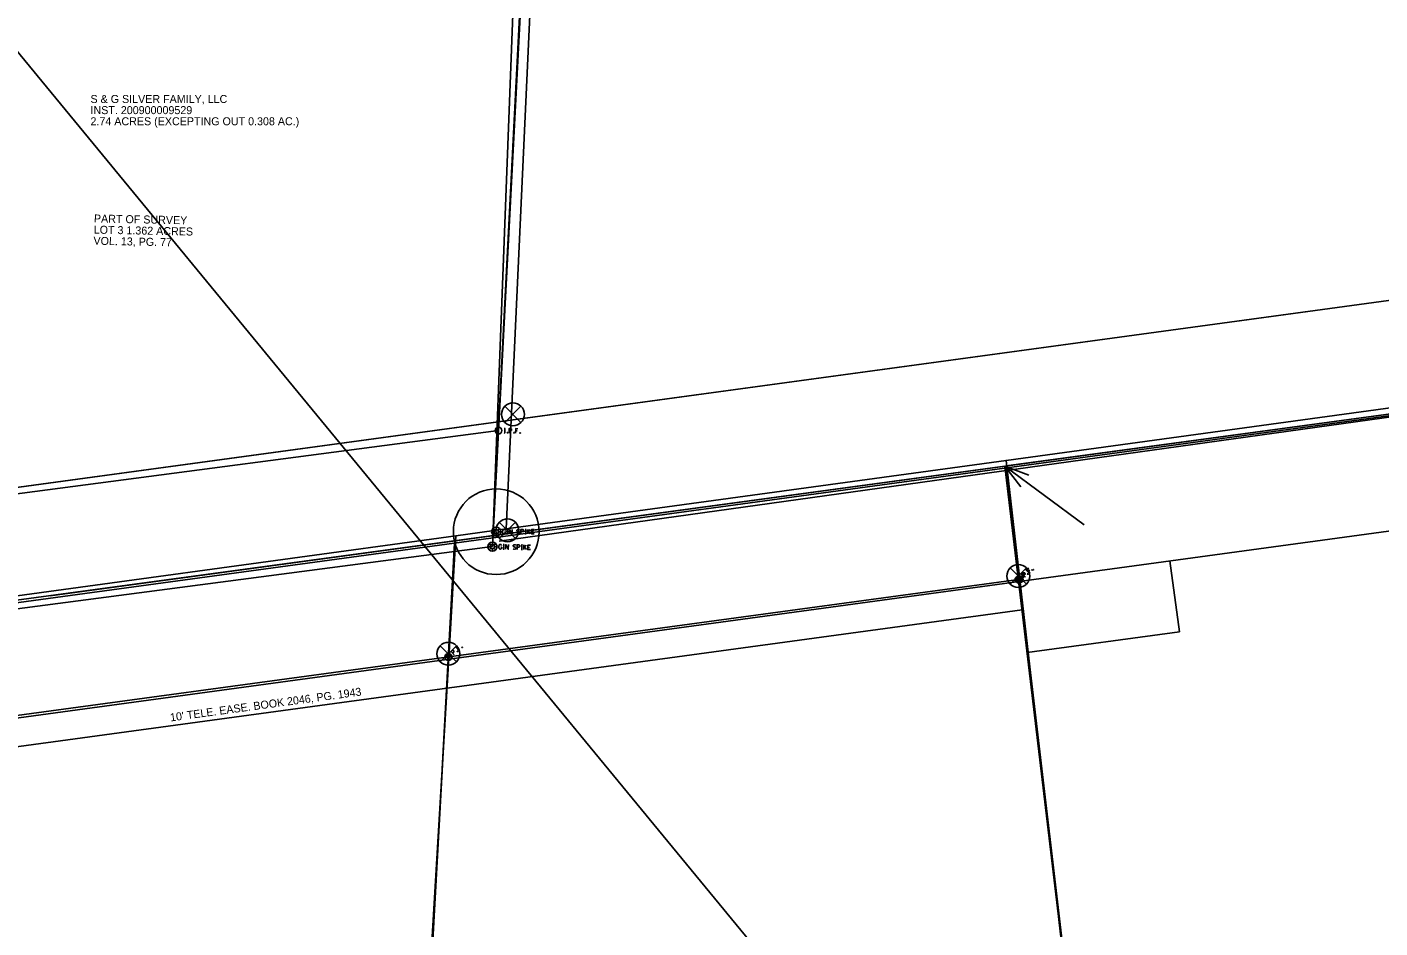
# Model space of a CAD drawing. Extents: x 1532954 to 1577849, y 698998 to 706606.
# Drawn here: x 1572033.3 to 1572506.6, y 702785.4 to 703100.9 of the extents above; entities that cross this region are included whole.
import ezdxf

# ---------------------------------------------------------------- set-up
doc = ezdxf.new("R2010")
doc.units = 0
for name, color, linetype in [('Default', 7, 'Continuous'), ('DV_X_Lot_Line', 7, 'Continuous'), ('DV_X_Property_Line', 7, 'Continuous'), ('GM_X_Major_Lake', 7, 'Continuous'), ('RW_X_Esmt_SH', 7, 'Continuous'), ('RW_X_Esmt_U', 7, 'Continuous'), ('RW_X_Text', 7, 'Continuous'), ('SC_Scratch1', 7, 'Continuous'), ('SC_Scratch10', 7, 'Continuous'), ('SC_Scratch2', 7, 'Continuous'), ('SC_Scratch3', 7, 'Continuous'), ('SC_Scratch4', 7, 'Continuous'), ('SC_Scratch9', 7, 'Continuous'), ('SV_X_Control_Cells_Found', 7, 'Continuous')]:
    doc.layers.add(name, color=color, linetype=linetype)

msp = doc.modelspace()

# ---------------------------------------------------------------- linework, layer by layer
at = {"layer": 'Default'}
for p, q in [((1572200.46, 702968.09), (1572206.12, 702962.43)), ((1572200.46, 702962.43), (1572206.12, 702968.09)), ((1572203.29, 702965.26), (1572203.29, 702965.26)), ((1572198.54, 702927.46), (1572204.2, 702921.8)), ((1572198.54, 702921.8), (1572204.2, 702927.46)), ((1572201.37, 702924.63), (1572201.37, 702924.63)), ((1572377.28, 702911.48), (1572382.94, 702905.82)), ((1572377.28, 702905.82), (1572382.94, 702911.48)), ((1572380.11, 702908.65), (1572380.11, 702908.65)), ((1572177.88, 702884.27), (1572183.54, 702878.61)), ((1572177.88, 702878.61), (1572183.54, 702884.27)), ((1572180.71, 702881.44), (1572180.71, 702881.44))]:
    msp.add_line(p, q, dxfattribs=at)
for centre in [(1572203.29, 702965.26), (1572201.37, 702924.63), (1572380.11, 702908.65), (1572180.71, 702881.44)]:
    msp.add_circle(centre, 4, dxfattribs=at)
at = {"layer": 'DV_X_Lot_Line'}
msp.add_line((1572166.48, 702619.22), (1572182.89, 702920.2), dxfattribs=at)
at = {"layer": 'DV_X_Property_Line'}
for p, q in [((1572245.38, 703873.46), (1572196.21, 702922.02)), ((1572416.09, 702605.27), (1572375.54, 702946.46))]:
    msp.add_line(p, q, dxfattribs=at)
at = {"layer": 'GM_X_Major_Lake'}
for p, q in [((1572436.47, 702889.16), (1572433.1, 702913.93)), ((1572383.21, 702881.9), (1572380.26, 702906.73)), ((1572383.21, 702881.9), (1572436.47, 702889.16))]:
    msp.add_line(p, q, dxfattribs=at)
at = {"layer": 'RW_X_Esmt_SH'}
for p, q in [((1571959, 702849.32), (1574870.56, 703246.15)), ((1571963.78, 702930.71), (1573359.47, 703120.93))]:
    msp.add_line(p, q, dxfattribs=at)
at = {"layer": 'RW_X_Esmt_U'}
msp.add_line((1571958.43, 702839.15), (1572381.44, 702896.8), dxfattribs=at)
at = {"layer": 'SC_Scratch1'}
for points in [[(1572687.31, 702991.85), (1572375.87, 702949.15), (1572200.89, 702925.16), (1572202.78, 702965.79), (1572209.37, 703107.62), (1572211.69, 703157.56), (1572219.71, 703329.96), (1572219.71, 703329.96), (1572224.35, 703429.86), (1572229.46, 703539.74), (1572237.01, 703702.1), (1572244.56, 703864.45), (1573202.26, 703819.91)], [(1572365.62, 701708.75), (1572371.48, 701808.58), (1572376.97, 701902.02), (1572377.3, 701908.41), (1572382.44, 702008.28), (1572387.57, 702108.15), (1572392.71, 702208.02), (1572397.85, 702307.89), (1572401.43, 702377.55), (1572403.22, 702407.75), (1572409.15, 702507.57), (1572415.08, 702607.4), (1572380.43, 702909.4), (1572375.87, 702949.15), (1572687.31, 702991.85), (1572800.34, 703007.35), (1572915.11, 703023.08), (1572964.59, 703029.87), (1572962.2, 702989.16), (1572818.71, 700543.9)]]:
    msp.add_lwpolyline(points, dxfattribs=at)
for points in [[(1572183.37, 702922.76), (1571930.88, 702888.14), (1571940.7, 703099.36), (1571941.66, 703120.07), (1571956.64, 703119.37), (1572131.42, 703111.24), (1572209.37, 703107.62), (1572202.78, 702965.79), (1572200.89, 702925.16)], [(1572380.43, 702909.4), (1572415.08, 702607.4), (1572165.51, 702622.06), (1572180.96, 702882.05), (1572183.37, 702922.76), (1572200.89, 702925.16), (1572375.87, 702949.15)], [(1572165.51, 702622.06), (1571940.9, 702635.26), (1571915.94, 702636.73), (1571918.93, 702687.02), (1571930.88, 702888.14), (1572183.37, 702922.76), (1572180.96, 702882.05)]]:
    msp.add_lwpolyline(points, close=True, dxfattribs=at)
at = {"layer": 'SC_Scratch10'}
for p, q in [((1571190.11, 702825.26), (1574958.12, 703338.82)), ((1571190.11, 702825.26), (1574958.12, 703338.82)), ((1571190.11, 702825.26), (1574958.12, 703338.82)), ((1571195.51, 702785.63), (1574963.52, 703299.19)), ((1571200.91, 702745.99), (1574968.92, 703259.55))]:
    msp.add_line(p, q, dxfattribs=at)
at = {"layer": 'SC_Scratch2'}
for p, q in [((1572196.21, 702922.02), (1572232.72, 703874.03)), ((1573640.53, 701135.41), (1571969.28, 703165.9)), ((1572679.74, 702987.92), (1572198.47, 702920.82))]:
    msp.add_line(p, q, dxfattribs=at)
at = {"layer": 'SC_Scratch3'}
for p, q in [((1572196.13, 702918.96), (1572235.66, 703675.7)), ((1571931.04, 702886.78), (1572682.15, 702988.83)), ((1572198.25, 702959.58), (1571957.98, 702928.04)), ((1571931.04, 702886.78), (1572375.46, 702947.16)), ((1572375.46, 702947.16), (1572416.09, 702605.27)), ((1572196.13, 702918.96), (1571335.92, 702806.05)), ((1572166.48, 702619.22), (1572182.93, 702921)), ((1572195.38, 702918.98), (1572194.53, 702918.99)), ((1572195.59, 702918.44), (1572194.98, 702917.85)), ((1572195.61, 702919.5), (1572195.02, 702920.11)), ((1572196.15, 702919.71), (1572196.16, 702920.56)), ((1572196.65, 702918.42), (1572197.24, 702917.81)), ((1572196.67, 702919.48), (1572197.28, 702920.07)), ((1572196.88, 702918.95), (1572197.73, 702918.93)), ((1572196.11, 702918.21), (1572196.1, 702917.36)), ((1571969.14, 702851.59), (1572380.18, 702907.43))]:
    msp.add_line(p, q, dxfattribs=at)
for points in [[(1572200.25, 702958.74), (1572200.6, 702958.73)], [(1572200.28, 702960.34), (1572200.63, 702960.33)], [(1572200.43, 702958.74), (1572200.46, 702960.34)], [(1572201.39, 702958.93), (1572201.44, 702958.93), (1572201.48, 702958.91), (1572201.51, 702958.85), (1572201.51, 702958.79), (1572201.47, 702958.74), (1572201.44, 702958.72), (1572201.38, 702958.72), (1572201.35, 702958.74), (1572201.32, 702958.8), (1572201.32, 702958.86), (1572201.36, 702958.91), (1572201.39, 702958.93)], [(1572201.99, 702958.71), (1572202.02, 702960.31), (1572202.55, 702960.3), (1572202.61, 702960.28), (1572202.68, 702960.25), (1572202.72, 702960.23), (1572202.75, 702960.2), (1572202.79, 702960.14), (1572202.82, 702960.08), (1572202.84, 702959.97), (1572202.84, 702959.82), (1572202.83, 702959.77), (1572202.8, 702959.7), (1572202.76, 702959.61), (1572202.71, 702959.57), (1572202.68, 702959.55), (1572202.62, 702959.52), (1572202.54, 702959.51), (1572202.01, 702959.52)], [(1572203.64, 702958.89), (1572203.69, 702958.89), (1572203.73, 702958.86), (1572203.76, 702958.81), (1572203.76, 702958.75), (1572203.72, 702958.7), (1572203.69, 702958.67), (1572203.63, 702958.67), (1572203.6, 702958.7), (1572203.57, 702958.75), (1572203.57, 702958.81), (1572203.6, 702958.86), (1572203.64, 702958.89)], [(1572205.03, 702960.25), (1572204.27, 702960.26), (1572204.24, 702958.66)], [(1572204.26, 702959.48), (1572204.8, 702959.47)], [(1572205.79, 702958.84), (1572205.84, 702958.84), (1572205.87, 702958.82), (1572205.91, 702958.77), (1572205.9, 702958.7), (1572205.87, 702958.65), (1572205.84, 702958.63), (1572205.78, 702958.63), (1572205.75, 702958.66), (1572205.72, 702958.71), (1572205.72, 702958.77), (1572205.75, 702958.82), (1572205.79, 702958.84)], [(1572199.33, 702919.38), (1572199.32, 702919.44), (1572199.28, 702919.51), (1572199.22, 702919.57), (1572199.13, 702919.65), (1572199.07, 702919.68), (1572199.02, 702919.69), (1572198.94, 702919.7), (1572198.79, 702919.71), (1572198.73, 702919.7), (1572198.69, 702919.68), (1572198.64, 702919.66), (1572198.54, 702919.59), (1572198.47, 702919.5), (1572198.43, 702919.4), (1572198.4, 702919.26), (1572198.38, 702919.06), (1572198.37, 702918.8), (1572198.38, 702918.58), (1572198.43, 702918.42), (1572198.5, 702918.26), (1572198.56, 702918.21), (1572198.63, 702918.16), (1572198.77, 702918.11), (1572198.91, 702918.1), (1572199.05, 702918.13), (1572199.1, 702918.15), (1572199.15, 702918.17), (1572199.2, 702918.22), (1572199.25, 702918.3), (1572199.31, 702918.41), (1572199.31, 702918.73), (1572199.05, 702918.73)], [(1572199.86, 702919.69), (1572200.27, 702919.68)], [(1572200.03, 702918.08), (1572200.06, 702919.68)], [(1572200.74, 702918.07), (1572200.77, 702919.67), (1572201.68, 702918.05), (1572201.71, 702919.65)], [(1572204.23, 702919.48), (1572204.21, 702919.51), (1572204.17, 702919.53), (1572204.06, 702919.57), (1572203.92, 702919.6), (1572203.82, 702919.61), (1572203.78, 702919.61), (1572203.61, 702919.57), (1572203.47, 702919.5), (1572203.38, 702919.4), (1572203.36, 702919.3), (1572203.36, 702919.22), (1572203.38, 702919.12), (1572203.48, 702919.03), (1572204.16, 702918.64), (1572204.22, 702918.59), (1572204.25, 702918.54), (1572204.27, 702918.46), (1572204.27, 702918.39), (1572204.26, 702918.31), (1572204.24, 702918.26), (1572204.22, 702918.2), (1572204.19, 702918.15), (1572204.16, 702918.11), (1572204.13, 702918.07), (1572204.09, 702918.05), (1572204.04, 702918.03), (1572204, 702918.01), (1572203.89, 702918), (1572203.71, 702918.01), (1572203.6, 702918.03), (1572203.43, 702918.13), (1572203.33, 702918.2)], [(1572204.74, 702917.99), (1572204.77, 702919.59), (1572205.38, 702919.57), (1572205.44, 702919.56), (1572205.53, 702919.53), (1572205.57, 702919.51), (1572205.6, 702919.48), (1572205.65, 702919.42), (1572205.69, 702919.35), (1572205.71, 702919.25), (1572205.71, 702919.1), (1572205.7, 702919.05), (1572205.67, 702918.98), (1572205.62, 702918.89), (1572205.57, 702918.85), (1572205.53, 702918.83), (1572205.46, 702918.8), (1572205.36, 702918.79), (1572204.76, 702918.8)], [(1572206.26, 702919.56), (1572206.66, 702919.55)], [(1572206.43, 702917.95), (1572206.46, 702919.55)], [(1572207.17, 702919.54), (1572207.13, 702917.94)], [(1572207.9, 702919.52), (1572207.15, 702918.52)], [(1572207.39, 702918.84), (1572207.99, 702917.92)], [(1572209.4, 702919.49), (1572208.53, 702919.51), (1572208.5, 702917.91), (1572209.43, 702917.89)], [(1572208.51, 702918.72), (1572209.13, 702918.7)], [(1572199.83, 702918.09), (1572200.23, 702918.08)], [(1572206.23, 702917.96), (1572206.63, 702917.95)], [(1572382.2, 702908.17), (1572381.13, 702909.36), (1572381.53, 702909.72), (1572381.58, 702909.74), (1572381.65, 702909.78), (1572381.69, 702909.78), (1572381.73, 702909.78), (1572381.81, 702909.77), (1572381.88, 702909.74), (1572381.96, 702909.68), (1572382.06, 702909.57), (1572382.09, 702909.52), (1572382.12, 702909.45), (1572382.15, 702909.36), (1572382.14, 702909.3), (1572382.13, 702909.26), (1572382.11, 702909.2), (1572382.05, 702909.13), (1572381.65, 702908.78)], [(1572383.37, 702911.37), (1572382.81, 702910.86), (1572383.88, 702909.67)], [(1572383.28, 702909.43), (1572383.32, 702909.46), (1572383.36, 702909.47), (1572383.42, 702909.45), (1572383.46, 702909.41), (1572383.47, 702909.35), (1572383.47, 702909.31), (1572383.42, 702909.27), (1572383.38, 702909.27), (1572383.32, 702909.28), (1572383.28, 702909.33), (1572383.27, 702909.39), (1572383.28, 702909.43)], [(1572383.33, 702910.28), (1572383.73, 702910.64)], [(1572384.88, 702910.86), (1572384.92, 702910.9), (1572384.96, 702910.9), (1572385.02, 702910.89), (1572385.06, 702910.84), (1572385.07, 702910.78), (1572385.07, 702910.74), (1572385.02, 702910.7), (1572384.98, 702910.7), (1572384.92, 702910.72), (1572384.88, 702910.76), (1572384.87, 702910.82), (1572384.88, 702910.86)], [(1572182.73, 702881.07), (1572181.66, 702882.26), (1572182.06, 702882.62), (1572182.11, 702882.64), (1572182.18, 702882.68), (1572182.22, 702882.68), (1572182.26, 702882.68), (1572182.34, 702882.66), (1572182.41, 702882.64), (1572182.49, 702882.58), (1572182.59, 702882.47), (1572182.62, 702882.42), (1572182.65, 702882.35), (1572182.68, 702882.26), (1572182.67, 702882.2), (1572182.66, 702882.16), (1572182.64, 702882.1), (1572182.58, 702882.03), (1572182.19, 702881.68)], [(1572183.9, 702884.27), (1572183.34, 702883.76), (1572184.41, 702882.57)], [(1572183.81, 702882.33), (1572183.85, 702882.36), (1572183.89, 702882.37), (1572183.95, 702882.35), (1572183.99, 702882.3), (1572184, 702882.24), (1572184, 702882.2), (1572183.96, 702882.17), (1572183.91, 702882.16), (1572183.86, 702882.18), (1572183.81, 702882.23), (1572183.8, 702882.29), (1572183.81, 702882.33)], [(1572183.86, 702883.18), (1572184.26, 702883.54)], [(1572185.41, 702883.76), (1572185.45, 702883.8), (1572185.49, 702883.8), (1572185.55, 702883.79), (1572185.6, 702883.74), (1572185.6, 702883.68), (1572185.6, 702883.64), (1572185.56, 702883.6), (1572185.51, 702883.6), (1572185.46, 702883.61), (1572185.41, 702883.66), (1572185.4, 702883.72), (1572185.41, 702883.76)]]:
    msp.add_lwpolyline(points, dxfattribs=at)
for centre, radius in [((1572198.25, 702959.58), 1.2), ((1572196.13, 702918.96), 1.6), ((1572196.13, 702918.96), 0.75), ((1572380.18, 702907.43), 1.2), ((1572380.18, 702907.43), 0.495), ((1572180.71, 702880.33), 1.2), ((1572180.71, 702880.33), 0.495)]:
    msp.add_circle(centre, radius, dxfattribs=at)
at = {"layer": 'SC_Scratch4'}
for p, q in [((1572041.35, 702901.76), (1573006.23, 703032.86)), ((1572963.42, 703027), (1572375.91, 702947.21)), ((1572375.91, 702947.21), (1572416.09, 702605.27))]:
    msp.add_line(p, q, dxfattribs=at)
for points in [[(1572382.6, 702908.22), (1572381.53, 702909.42), (1572381.93, 702909.77), (1572381.98, 702909.8), (1572382.05, 702909.83), (1572382.09, 702909.83), (1572382.14, 702909.84), (1572382.21, 702909.82), (1572382.28, 702909.79), (1572382.36, 702909.73), (1572382.46, 702909.62), (1572382.49, 702909.58), (1572382.52, 702909.51), (1572382.55, 702909.41), (1572382.54, 702909.35), (1572382.53, 702909.31), (1572382.51, 702909.26), (1572382.45, 702909.19), (1572382.06, 702908.83)], [(1572383.77, 702911.43), (1572383.21, 702910.92), (1572384.28, 702909.73)], [(1572383.68, 702909.48), (1572383.72, 702909.52), (1572383.76, 702909.52), (1572383.82, 702909.51), (1572383.87, 702909.46), (1572383.87, 702909.4), (1572383.87, 702909.36), (1572383.83, 702909.32), (1572383.78, 702909.32), (1572383.73, 702909.33), (1572383.68, 702909.38), (1572383.67, 702909.44), (1572383.68, 702909.48)], [(1572383.73, 702910.34), (1572384.13, 702910.7)], [(1572385.28, 702910.92), (1572385.32, 702910.95), (1572385.37, 702910.96), (1572385.42, 702910.94), (1572385.47, 702910.89), (1572385.47, 702910.83), (1572385.47, 702910.79), (1572385.43, 702910.76), (1572385.38, 702910.75), (1572385.33, 702910.77), (1572385.28, 702910.82), (1572385.27, 702910.88), (1572385.28, 702910.92)]]:
    msp.add_lwpolyline(points, dxfattribs=at)
for radius in [1.2, 0.495]:
    msp.add_circle((1572380.58, 702907.49), radius, dxfattribs=at)
at = {"layer": 'SC_Scratch9'}
for q in [(1572403.11, 702926.6), (1572381.04, 702939.87), (1572383.81, 702943.97)]:
    msp.add_line((1572375.46, 702947.16), q, dxfattribs=at)
msp.add_circle((1572197.45, 702924.18), 15, dxfattribs=at)
at = {"layer": 'SV_X_Control_Cells_Found'}
for p, q in [((1572196.7, 702924.18), (1572195.85, 702924.18)), ((1572196.92, 702924.71), (1572196.32, 702925.32)), ((1572196.92, 702923.65), (1572196.32, 702923.05)), ((1572197.45, 702924.93), (1572197.45, 702925.78)), ((1572197.45, 702923.43), (1572197.45, 702922.58)), ((1572197.98, 702924.71), (1572198.58, 702925.32)), ((1572197.98, 702923.65), (1572198.58, 702923.05)), ((1572198.2, 702924.18), (1572199.05, 702924.18))]:
    msp.add_line(p, q, dxfattribs=at)
for points in [[(1572200.64, 702924.67), (1572200.62, 702924.73), (1572200.59, 702924.79), (1572200.52, 702924.86), (1572200.43, 702924.93), (1572200.37, 702924.96), (1572200.32, 702924.97), (1572200.25, 702924.98), (1572200.09, 702924.98), (1572200.03, 702924.97), (1572199.99, 702924.96), (1572199.94, 702924.93), (1572199.84, 702924.86), (1572199.78, 702924.77), (1572199.74, 702924.67), (1572199.72, 702924.53), (1572199.69, 702924.33), (1572199.69, 702924.06), (1572199.7, 702923.85), (1572199.75, 702923.69), (1572199.83, 702923.53), (1572199.89, 702923.48), (1572199.97, 702923.43), (1572200.11, 702923.38), (1572200.25, 702923.38), (1572200.38, 702923.41), (1572200.43, 702923.43), (1572200.48, 702923.46), (1572200.53, 702923.51), (1572200.59, 702923.59), (1572200.64, 702923.7), (1572200.64, 702924.01), (1572200.37, 702924.01)], [(1572201.16, 702924.98), (1572201.57, 702924.98)], [(1572201.16, 702923.38), (1572201.57, 702923.38)], [(1572201.37, 702923.38), (1572201.37, 702924.98)], [(1572202.07, 702923.38), (1572202.07, 702924.98), (1572203.02, 702923.38), (1572203.02, 702924.98)], [(1572205.54, 702924.87), (1572205.51, 702924.9), (1572205.47, 702924.92), (1572205.36, 702924.96), (1572205.22, 702924.98), (1572205.12, 702924.98), (1572205.08, 702924.98), (1572204.92, 702924.95), (1572204.78, 702924.87), (1572204.69, 702924.77), (1572204.67, 702924.67), (1572204.67, 702924.59), (1572204.69, 702924.49), (1572204.79, 702924.4), (1572205.49, 702924.03), (1572205.55, 702923.98), (1572205.57, 702923.93), (1572205.6, 702923.85), (1572205.6, 702923.77), (1572205.59, 702923.7), (1572205.57, 702923.65), (1572205.55, 702923.59), (1572205.52, 702923.53), (1572205.5, 702923.5), (1572205.46, 702923.46), (1572205.42, 702923.43), (1572205.37, 702923.41), (1572205.33, 702923.4), (1572205.22, 702923.38), (1572205.04, 702923.38), (1572204.93, 702923.41), (1572204.77, 702923.5), (1572204.67, 702923.57)], [(1572206.08, 702923.38), (1572206.08, 702924.98), (1572206.68, 702924.98), (1572206.75, 702924.97), (1572206.83, 702924.95), (1572206.87, 702924.92), (1572206.91, 702924.9), (1572206.96, 702924.83), (1572207, 702924.77), (1572207.02, 702924.67), (1572207.02, 702924.52), (1572207.01, 702924.47), (1572206.98, 702924.39), (1572206.93, 702924.3), (1572206.88, 702924.27), (1572206.85, 702924.24), (1572206.78, 702924.22), (1572206.68, 702924.2), (1572206.08, 702924.2)], [(1572207.56, 702924.98), (1572207.97, 702924.98)], [(1572207.56, 702923.38), (1572207.97, 702923.38)], [(1572207.77, 702923.38), (1572207.77, 702924.98)], [(1572208.47, 702924.98), (1572208.47, 702923.38)], [(1572209.2, 702924.98), (1572208.47, 702923.96)], [(1572208.71, 702924.29), (1572209.33, 702923.38)], [(1572210.7, 702924.98), (1572209.83, 702924.98), (1572209.83, 702923.38), (1572210.76, 702923.38)], [(1572209.83, 702924.19), (1572210.45, 702924.19)]]:
    msp.add_lwpolyline(points, dxfattribs=at)
for radius in [1.6, 0.75]:
    msp.add_circle((1572197.45, 702924.18), radius, dxfattribs=at)

# ---------------------------------------------------------------- texts
at = {"layer": 'RW_X_Text'}
for s, p in [('S & G SILVER FAMILY, LLC', (1572055.5, 703074.27)), ('INST. 200900009529', (1572055.5, 703070.37)), ('2.74 ACRES (EXCEPTING OUT 0.308 AC.)', (1572055.5, 703066.47))]:
    msp.add_text(s, height=2.8, dxfattribs=at).set_placement(p)
msp.add_text("10' TELE. EASE. BOOK 2046, PG. 1943", height=2.8, rotation=7.7687, dxfattribs=at).set_placement((1572083.53, 702857.73))
at = {"layer": 'SC_Scratch3'}
for s, p in [('PART OF SURVEY', (1572056.68, 703032.45)), ('VOL. 13, PG. 77', (1572056.52, 703024.65)), ('LOT 3 1.362 ACRES', (1572056.6, 703028.55))]:
    msp.add_text(s, height=2.8, rotation=358.8432, dxfattribs=at).set_placement(p)

doc.saveas('drawing.dxf')
